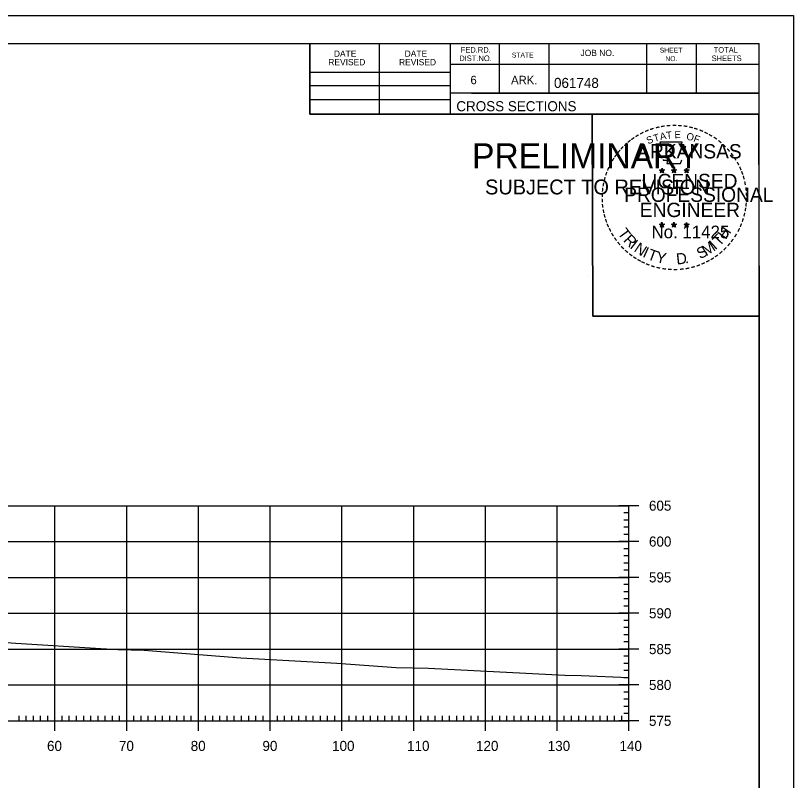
# Model space of a CAD drawing. Extents: x 961436 to 1372525, y 380079 to 2027791.
# Drawn here: x 1370245 to 1370353.4, y 380215.7 to 380322.4 of the extents above; entities that cross this region are included whole.
import ezdxf

# ---------------------------------------------------------------- set-up
doc = ezdxf.new("R2010")
doc.units = 0
for name, color, linetype in [('R_Axis', 7, 'Continuous'), ('R_Axis Annot', 7, 'Continuous'), ('R_Exist Surface', 7, 'Continuous'), ('R_Grid', 7, 'Continuous'), ('R_No Plot', 7, 'Continuous')]:
    doc.layers.add(name, color=color, linetype=linetype)

msp = doc.modelspace()

# ---------------------------------------------------------------- linework, layer by layer
at = {"layer": 'R_Axis'}
for p, q in [((1370331.9, 380254.06), (1370329.1, 380254.06)), ((1370330.5, 380224.06), (1370330.5, 380254.06)), ((1370330.5, 380253.06), (1370329.8, 380253.06)), ((1370330.5, 380252.06), (1370329.8, 380252.06)), ((1370330.5, 380251.06), (1370329.8, 380251.06)), ((1370330.5, 380250.06), (1370329.8, 380250.06)), ((1370331.9, 380249.06), (1370329.1, 380249.06)), ((1370330.5, 380248.06), (1370329.8, 380248.06)), ((1370330.5, 380247.06), (1370329.8, 380247.06)), ((1370330.5, 380246.06), (1370329.8, 380246.06)), ((1370330.5, 380245.06), (1370329.8, 380245.06)), ((1370331.9, 380244.06), (1370329.1, 380244.06)), ((1370330.5, 380243.06), (1370329.8, 380243.06)), ((1370330.5, 380242.06), (1370329.8, 380242.06)), ((1370330.5, 380241.06), (1370329.8, 380241.06)), ((1370330.5, 380240.06), (1370329.8, 380240.06)), ((1370331.9, 380239.06), (1370329.1, 380239.06)), ((1370330.5, 380238.06), (1370329.8, 380238.06)), ((1370330.5, 380237.06), (1370329.8, 380237.06)), ((1370330.5, 380236.06), (1370329.8, 380236.06)), ((1370330.5, 380235.06), (1370329.8, 380235.06)), ((1370331.9, 380234.06), (1370329.1, 380234.06)), ((1370330.5, 380233.06), (1370329.8, 380233.06)), ((1370330.5, 380232.06), (1370329.8, 380232.06)), ((1370330.5, 380231.06), (1370329.8, 380231.06)), ((1370330.5, 380230.06), (1370329.8, 380230.06)), ((1370331.9, 380229.06), (1370329.1, 380229.06)), ((1370330.5, 380228.06), (1370329.8, 380228.06)), ((1370330.5, 380227.06), (1370329.8, 380227.06)), ((1370250.5, 380222.66), (1370250.5, 380225.46)), ((1370260.5, 380222.66), (1370260.5, 380225.46)), ((1370270.5, 380222.66), (1370270.5, 380225.46)), ((1370280.5, 380222.66), (1370280.5, 380225.46)), ((1370290.5, 380222.66), (1370290.5, 380225.46)), ((1370300.5, 380222.66), (1370300.5, 380225.46)), ((1370310.5, 380222.66), (1370310.5, 380225.46)), ((1370320.5, 380222.66), (1370320.5, 380225.46)), ((1370330.5, 380226.06), (1370329.8, 380226.06)), ((1370330.5, 380222.66), (1370330.5, 380225.46)), ((1370050.5, 380224.06), (1370330.5, 380224.06)), ((1370245.5, 380224.06), (1370245.5, 380224.76)), ((1370246.5, 380224.06), (1370246.5, 380224.76)), ((1370247.5, 380224.06), (1370247.5, 380224.76)), ((1370248.5, 380224.06), (1370248.5, 380224.76)), ((1370249.5, 380224.06), (1370249.5, 380224.76)), ((1370251.5, 380224.06), (1370251.5, 380224.76)), ((1370252.5, 380224.06), (1370252.5, 380224.76)), ((1370253.5, 380224.06), (1370253.5, 380224.76)), ((1370254.5, 380224.06), (1370254.5, 380224.76)), ((1370255.5, 380224.06), (1370255.5, 380224.76)), ((1370256.5, 380224.06), (1370256.5, 380224.76)), ((1370257.5, 380224.06), (1370257.5, 380224.76)), ((1370258.5, 380224.06), (1370258.5, 380224.76)), ((1370259.5, 380224.06), (1370259.5, 380224.76)), ((1370261.5, 380224.06), (1370261.5, 380224.76)), ((1370262.5, 380224.06), (1370262.5, 380224.76)), ((1370263.5, 380224.06), (1370263.5, 380224.76)), ((1370264.5, 380224.06), (1370264.5, 380224.76)), ((1370265.5, 380224.06), (1370265.5, 380224.76)), ((1370266.5, 380224.06), (1370266.5, 380224.76)), ((1370267.5, 380224.06), (1370267.5, 380224.76)), ((1370268.5, 380224.06), (1370268.5, 380224.76)), ((1370269.5, 380224.06), (1370269.5, 380224.76)), ((1370271.5, 380224.06), (1370271.5, 380224.76)), ((1370272.5, 380224.06), (1370272.5, 380224.76)), ((1370273.5, 380224.06), (1370273.5, 380224.76)), ((1370274.5, 380224.06), (1370274.5, 380224.76)), ((1370275.5, 380224.06), (1370275.5, 380224.76)), ((1370276.5, 380224.06), (1370276.5, 380224.76)), ((1370277.5, 380224.06), (1370277.5, 380224.76)), ((1370278.5, 380224.06), (1370278.5, 380224.76)), ((1370279.5, 380224.06), (1370279.5, 380224.76)), ((1370281.5, 380224.06), (1370281.5, 380224.76)), ((1370282.5, 380224.06), (1370282.5, 380224.76)), ((1370283.5, 380224.06), (1370283.5, 380224.76)), ((1370284.5, 380224.06), (1370284.5, 380224.76)), ((1370285.5, 380224.06), (1370285.5, 380224.76)), ((1370286.5, 380224.06), (1370286.5, 380224.76)), ((1370287.5, 380224.06), (1370287.5, 380224.76)), ((1370288.5, 380224.06), (1370288.5, 380224.76)), ((1370289.5, 380224.06), (1370289.5, 380224.76)), ((1370291.5, 380224.06), (1370291.5, 380224.76)), ((1370292.5, 380224.06), (1370292.5, 380224.76)), ((1370293.5, 380224.06), (1370293.5, 380224.76)), ((1370294.5, 380224.06), (1370294.5, 380224.76)), ((1370295.5, 380224.06), (1370295.5, 380224.76)), ((1370296.5, 380224.06), (1370296.5, 380224.76)), ((1370297.5, 380224.06), (1370297.5, 380224.76)), ((1370298.5, 380224.06), (1370298.5, 380224.76)), ((1370299.5, 380224.06), (1370299.5, 380224.76)), ((1370301.5, 380224.06), (1370301.5, 380224.76)), ((1370302.5, 380224.06), (1370302.5, 380224.76)), ((1370303.5, 380224.06), (1370303.5, 380224.76)), ((1370304.5, 380224.06), (1370304.5, 380224.76)), ((1370305.5, 380224.06), (1370305.5, 380224.76)), ((1370306.5, 380224.06), (1370306.5, 380224.76)), ((1370307.5, 380224.06), (1370307.5, 380224.76)), ((1370308.5, 380224.06), (1370308.5, 380224.76)), ((1370309.5, 380224.06), (1370309.5, 380224.76)), ((1370311.5, 380224.06), (1370311.5, 380224.76)), ((1370312.5, 380224.06), (1370312.5, 380224.76)), ((1370313.5, 380224.06), (1370313.5, 380224.76)), ((1370314.5, 380224.06), (1370314.5, 380224.76)), ((1370315.5, 380224.06), (1370315.5, 380224.76)), ((1370316.5, 380224.06), (1370316.5, 380224.76)), ((1370317.5, 380224.06), (1370317.5, 380224.76)), ((1370318.5, 380224.06), (1370318.5, 380224.76)), ((1370319.5, 380224.06), (1370319.5, 380224.76)), ((1370321.5, 380224.06), (1370321.5, 380224.76)), ((1370322.5, 380224.06), (1370322.5, 380224.76)), ((1370323.5, 380224.06), (1370323.5, 380224.76)), ((1370324.5, 380224.06), (1370324.5, 380224.76)), ((1370325.5, 380224.06), (1370325.5, 380224.76)), ((1370326.5, 380224.06), (1370326.5, 380224.76)), ((1370327.5, 380224.06), (1370327.5, 380224.76)), ((1370328.5, 380224.06), (1370328.5, 380224.76)), ((1370331.9, 380224.06), (1370329.1, 380224.06)), ((1370329.5, 380224.06), (1370329.5, 380224.76)), ((1370330.5, 380225.06), (1370329.8, 380225.06))]:
    msp.add_line(p, q, dxfattribs=at)
at = {"layer": 'R_Exist Surface'}
msp.add_lwpolyline([(1370243.11, 380235.04), (1370245.03, 380234.91), (1370256.9, 380234.13), (1370259.27, 380234.01), (1370262.93, 380233.9), (1370276.43, 380232.83), (1370289.8, 380232.08), (1370298.07, 380231.5), (1370302.55, 380231.4), (1370321.57, 380230.45), (1370323.84, 380230.38), (1370330.5, 380230.11)], dxfattribs=at)
at = {"layer": 'R_Grid'}
for p, q in [((1370050.5, 380254.06), (1370330.5, 380254.06)), ((1370250.5, 380224.06), (1370250.5, 380254.06)), ((1370260.5, 380224.06), (1370260.5, 380254.06)), ((1370270.5, 380224.06), (1370270.5, 380254.06)), ((1370280.5, 380224.06), (1370280.5, 380254.06)), ((1370290.5, 380224.06), (1370290.5, 380254.06)), ((1370300.5, 380224.06), (1370300.5, 380254.06)), ((1370310.5, 380224.06), (1370310.5, 380254.06)), ((1370320.5, 380224.06), (1370320.5, 380254.06)), ((1370330.5, 380224.06), (1370330.5, 380254.06)), ((1370050.5, 380249.06), (1370330.5, 380249.06)), ((1370050.5, 380244.06), (1370330.5, 380244.06)), ((1370050.5, 380239.06), (1370330.5, 380239.06)), ((1370050.5, 380234.06), (1370330.5, 380234.06)), ((1370050.5, 380229.06), (1370330.5, 380229.06)), ((1370050.5, 380224.06), (1370330.5, 380224.06))]:
    msp.add_line(p, q, dxfattribs=at)
at = {"layer": 'R_No Plot'}
for p, q in [((1370020.1, 380322.41), (1370353.44, 380322.41)), ((1370032.5, 380318.52), (1370348.68, 380318.52)), ((1370286.04, 380308.64), (1370286.04, 380318.52)), ((1370295.72, 380308.64), (1370295.72, 380318.52)), ((1370305.58, 380318.52), (1370305.58, 380308.64)), ((1370312.42, 380318.52), (1370312.42, 380311.58)), ((1370319.36, 380318.52), (1370319.36, 380311.58)), ((1370332.94, 380318.52), (1370332.94, 380311.58)), ((1370339.88, 380318.52), (1370339.88, 380311.58)), ((1370348.68, 380113.06), (1370348.68, 380318.52)), ((1370348.68, 380315.58), (1370305.58, 380315.58)), ((1370348.68, 380315.6), (1370348.68, 380315.6)), ((1370286.04, 380314.5), (1370305.58, 380314.5)), ((1370286.04, 380312.64), (1370305.58, 380312.64)), ((1370348.68, 380311.58), (1370305.58, 380311.58)), ((1370308.54, 380311.58), (1370348.68, 380311.58)), ((1370286.04, 380310.7), (1370305.58, 380310.7)), ((1370348.68, 380308.64), (1370286.04, 380308.64)), ((1370335.12, 380301.15), (1370335.08, 380300.9)), ((1370335.12, 380300.78), (1370335.12, 380301.15)), ((1370335.12, 380301.15), (1370335.17, 380300.9)), ((1370336.79, 380301.15), (1370336.75, 380300.9)), ((1370336.79, 380300.78), (1370336.79, 380301.15)), ((1370336.79, 380301.15), (1370336.84, 380300.9)), ((1370338.55, 380301.14), (1370338.51, 380300.88)), ((1370338.55, 380300.77), (1370338.55, 380301.14)), ((1370338.55, 380301.14), (1370338.6, 380300.89)), ((1370334.77, 380300.89), (1370335.12, 380300.78)), ((1370334.77, 380300.89), (1370335.02, 380300.85)), ((1370334.77, 380300.89), (1370335.01, 380300.77)), ((1370334.9, 380300.49), (1370335.12, 380300.78)), ((1370334.9, 380300.49), (1370335.03, 380300.73)), ((1370334.9, 380300.49), (1370335.12, 380300.7)), ((1370335.47, 380300.89), (1370335.12, 380300.78)), ((1370335.33, 380300.49), (1370335.12, 380300.78)), ((1370335.33, 380300.49), (1370335.12, 380300.7)), ((1370335.47, 380300.89), (1370335.18, 380300.85)), ((1370335.33, 380300.49), (1370335.19, 380300.78)), ((1370335.47, 380300.89), (1370335.26, 380300.79)), ((1370336.44, 380300.89), (1370336.79, 380300.78)), ((1370336.44, 380300.89), (1370336.69, 380300.85)), ((1370336.44, 380300.89), (1370336.68, 380300.77)), ((1370336.57, 380300.49), (1370336.79, 380300.78)), ((1370336.57, 380300.49), (1370336.7, 380300.73)), ((1370336.57, 380300.49), (1370336.79, 380300.7)), ((1370337.14, 380300.89), (1370336.79, 380300.78)), ((1370337, 380300.49), (1370336.79, 380300.78)), ((1370337, 380300.49), (1370336.79, 380300.7)), ((1370337.14, 380300.89), (1370336.85, 380300.85)), ((1370337, 380300.49), (1370336.86, 380300.78)), ((1370337.14, 380300.89), (1370336.93, 380300.79)), ((1370338.2, 380300.88), (1370338.55, 380300.77)), ((1370338.2, 380300.88), (1370338.46, 380300.84)), ((1370338.2, 380300.88), (1370338.44, 380300.76)), ((1370338.34, 380300.47), (1370338.55, 380300.77)), ((1370338.34, 380300.47), (1370338.46, 380300.72)), ((1370338.34, 380300.47), (1370338.55, 380300.69)), ((1370338.9, 380300.88), (1370338.55, 380300.77)), ((1370338.77, 380300.47), (1370338.55, 380300.77)), ((1370338.77, 380300.47), (1370338.55, 380300.69)), ((1370338.9, 380300.88), (1370338.61, 380300.83)), ((1370338.77, 380300.47), (1370338.63, 380300.77)), ((1370338.9, 380300.88), (1370338.7, 380300.78)), ((1370335.11, 380293.58), (1370335.07, 380293.32)), ((1370335.11, 380293.21), (1370335.11, 380293.58)), ((1370335.11, 380293.58), (1370335.16, 380293.33)), ((1370336.78, 380293.58), (1370336.74, 380293.32)), ((1370336.78, 380293.21), (1370336.78, 380293.58)), ((1370336.78, 380293.58), (1370336.83, 380293.33)), ((1370338.55, 380293.57), (1370338.51, 380293.31)), ((1370338.55, 380293.2), (1370338.55, 380293.57)), ((1370338.55, 380293.57), (1370338.6, 380293.32)), ((1370334.77, 380293.32), (1370335.11, 380293.21)), ((1370334.77, 380293.32), (1370335.02, 380293.28)), ((1370334.77, 380293.32), (1370335, 380293.2)), ((1370334.9, 380292.91), (1370335.11, 380293.21)), ((1370334.9, 380292.91), (1370335.02, 380293.16)), ((1370334.9, 380292.91), (1370335.11, 380293.13)), ((1370335.46, 380293.32), (1370335.11, 380293.21)), ((1370335.33, 380292.91), (1370335.11, 380293.21)), ((1370335.33, 380292.91), (1370335.11, 380293.13)), ((1370335.46, 380293.32), (1370335.18, 380293.27)), ((1370335.33, 380292.91), (1370335.19, 380293.2)), ((1370335.46, 380293.32), (1370335.26, 380293.22)), ((1370336.43, 380293.32), (1370336.78, 380293.21)), ((1370336.43, 380293.32), (1370336.69, 380293.28)), ((1370336.43, 380293.32), (1370336.67, 380293.2)), ((1370336.57, 380292.91), (1370336.78, 380293.21)), ((1370336.57, 380292.91), (1370336.69, 380293.16)), ((1370336.57, 380292.91), (1370336.78, 380293.13)), ((1370337.13, 380293.32), (1370336.78, 380293.21)), ((1370337, 380292.91), (1370336.78, 380293.21)), ((1370337, 380292.91), (1370336.78, 380293.13)), ((1370337.13, 380293.32), (1370336.84, 380293.27)), ((1370337, 380292.91), (1370336.86, 380293.2)), ((1370337.13, 380293.32), (1370336.93, 380293.22)), ((1370338.2, 380293.31), (1370338.55, 380293.2)), ((1370338.2, 380293.31), (1370338.45, 380293.27)), ((1370338.2, 380293.31), (1370338.44, 380293.19)), ((1370338.33, 380292.9), (1370338.55, 380293.2)), ((1370338.33, 380292.9), (1370338.46, 380293.15)), ((1370338.33, 380292.9), (1370338.55, 380293.12)), ((1370338.9, 380293.31), (1370338.55, 380293.2)), ((1370338.76, 380292.9), (1370338.55, 380293.2)), ((1370338.76, 380292.9), (1370338.55, 380293.12)), ((1370338.9, 380293.31), (1370338.61, 380293.26)), ((1370338.76, 380292.9), (1370338.63, 380293.19)), ((1370338.9, 380293.31), (1370338.69, 380293.21)), ((1370324.72, 380286.18), (1370324.72, 380286.18))]:
    msp.add_line(p, q, dxfattribs=at)
for points in [[(1370020.1, 380322.41), (1370353.44, 380322.41), (1370353.44, 380109.08), (1370020.1, 380109.08)], [(1370266.42, 380318.52), (1370286.04, 380318.52), (1370286.04, 380308.64), (1370302.16, 380308.64), (1370325.36, 380308.64), (1370325.48, 380280.48), (1370348.68, 380280.48), (1370348.68, 380113.06), (1370032.5, 380113.06), (1370032.5, 380318.52)], [(1370325.36, 380308.64), (1370348.56, 380308.64), (1370348.68, 380280.48), (1370325.48, 380280.48)]]:
    msp.add_lwpolyline(points, close=True, dxfattribs=at)
for points in [[(1370334.81, 380304.77), (1370335.08, 380303.95)], [(1370338.32, 380303.85), (1370338.46, 380304.13), (1370337.78, 380304.11), (1370337.93, 380304.77), (1370334.81, 380304.77)], [(1370335.3, 380302.35), (1370335.3, 380302.26), (1370335.87, 380302.24), (1370335.81, 380301.77), (1370337.68, 380301.77), (1370337.88, 380302.31)], [(1370335.12, 380301.15), (1370335.33, 380300.49), (1370334.77, 380300.89), (1370335.47, 380300.89), (1370334.9, 380300.49), (1370335.12, 380301.15)], [(1370336.79, 380301.15), (1370337, 380300.49), (1370336.44, 380300.89), (1370337.14, 380300.89), (1370336.57, 380300.49), (1370336.79, 380301.15)], [(1370338.55, 380301.14), (1370338.77, 380300.47), (1370338.2, 380300.88), (1370338.9, 380300.88), (1370338.34, 380300.47), (1370338.55, 380301.14)], [(1370335.11, 380293.58), (1370335.33, 380292.91), (1370334.77, 380293.32), (1370335.46, 380293.32), (1370334.9, 380292.91), (1370335.11, 380293.58)], [(1370336.78, 380293.58), (1370337, 380292.91), (1370336.43, 380293.32), (1370337.13, 380293.32), (1370336.57, 380292.91), (1370336.78, 380293.58)], [(1370338.55, 380293.57), (1370338.76, 380292.9), (1370338.2, 380293.31), (1370338.9, 380293.31), (1370338.33, 380292.9), (1370338.55, 380293.57)]]:
    msp.add_lwpolyline(points, dxfattribs=at)
for centre, radius in [((1370335.12, 380300.78), 0.172), ((1370335.12, 380300.78), 0.145), ((1370335.12, 380300.78), 0.116), ((1370335.12, 380300.78), 0.0991), ((1370335.12, 380300.78), 0.0747), ((1370335.12, 380300.78), 0.0495), ((1370335.12, 380300.78), 0.0296), ((1370336.79, 380300.78), 0.172), ((1370336.79, 380300.78), 0.145), ((1370336.79, 380300.78), 0.116), ((1370336.79, 380300.78), 0.0991), ((1370336.79, 380300.78), 0.0747), ((1370336.79, 380300.78), 0.0495), ((1370336.79, 380300.78), 0.0296), ((1370338.55, 380300.77), 0.172), ((1370338.55, 380300.77), 0.145), ((1370338.55, 380300.77), 0.116), ((1370338.55, 380300.77), 0.0991), ((1370338.55, 380300.77), 0.0747), ((1370338.55, 380300.77), 0.0495), ((1370338.55, 380300.77), 0.0296), ((1370335.11, 380293.21), 0.172), ((1370335.11, 380293.21), 0.145), ((1370335.11, 380293.21), 0.116), ((1370335.11, 380293.21), 0.0991), ((1370335.11, 380293.21), 0.0747), ((1370335.11, 380293.21), 0.0495), ((1370335.11, 380293.21), 0.0296), ((1370336.78, 380293.21), 0.172), ((1370336.78, 380293.21), 0.145), ((1370336.78, 380293.21), 0.116), ((1370336.78, 380293.21), 0.0991), ((1370336.78, 380293.21), 0.0747), ((1370336.78, 380293.21), 0.0495), ((1370336.78, 380293.21), 0.0296), ((1370338.55, 380293.2), 0.172), ((1370338.55, 380293.2), 0.145), ((1370338.55, 380293.2), 0.116), ((1370338.55, 380293.2), 0.0991), ((1370338.55, 380293.2), 0.0747), ((1370338.55, 380293.2), 0.0495), ((1370338.55, 380293.2), 0.0296)]:
    msp.add_circle(centre, radius, dxfattribs=at)

# ---------------------------------------------------------------- texts
at = {"layer": 'R_Axis Annot'}
for s, p in [('605', (1370333.3, 380253.36)), ('600', (1370333.3, 380248.36)), ('595', (1370333.3, 380243.36)), ('590', (1370333.3, 380238.36)), ('585', (1370333.3, 380233.36)), ('580', (1370333.3, 380228.36)), ('575', (1370333.3, 380223.36)), ('60', (1370249.39, 380219.86)), ('70', (1370259.42, 380219.86)), ('80', (1370269.42, 380219.86)), ('90', (1370279.42, 380219.86)), ('100', (1370289.13, 380219.86)), ('110', (1370299.58, 380219.86)), ('120', (1370309.19, 380219.86)), ('130', (1370319.19, 380219.86)), ('140', (1370329.19, 380219.86))]:
    msp.add_text(s, height=1.4, dxfattribs=at).set_placement(p)
at = {"layer": 'R_No Plot'}
for s, height, rotation, p in [('DATE', 0.879, 360, (1370289.38, 380316.66)), ('DATE', 0.879, 360, (1370299.24, 380316.66)), ('FED.RD.', 0.782, 360, (1370307.06, 380317.24)), ('JOB NO.', 0.879, 360, (1370323.76, 380316.76)), ('SHEET', 0.684, 360, (1370334.8, 380317.24)), ('TOTAL', 0.782, 360, (1370342.32, 380317.24)), ('REVISED', 0.879, 360, (1370288.6, 380315.48)), ('REVISED', 0.879, 360, (1370298.46, 380315.48)), ('DIST.NO.', 0.782, 360, (1370306.86, 380316.06)), ('STATE', 0.684, 360, (1370314.18, 380316.56)), ('NO.', 0.684, 360, (1370335.58, 380316.06)), ('SHEETS', 0.782, 360, (1370342.04, 380316.06)), ('6', 1.17, 360, (1370308.42, 380312.84)), ('ARK.', 1.172, 360, (1370314.08, 380312.84)), ('061748', 1.4, 360, (1370320.06, 380312.32)), ('CROSS SECTIONS', 1.4, 360, (1370306.45, 380309.07)), ('-', 1.6, 24.3072, (1370332.92, 380305.63)), ('-', 1.6, 19.1761, (1370333.56, 380305.9)), ('-', 1.6, 13.6301, (1370334.31, 380306.14)), ('-', 1.6, 10.2193, (1370334.99, 380306.3)), ('-', 1.6, 5.8968, (1370335.72, 380306.41)), ('-', 1.6, 0.1862, (1370336.49, 380306.48)), ('-', 1.6, 357.743, (1370337.21, 380306.47)), ('-', 1.6, 352.1617, (1370337.95, 380306.42)), ('-', 1.6, 347.2049, (1370338.67, 380306.3)), ('-', 1.6, 342.3362, (1370339.31, 380306.15)), ('-', 1.6, 337.8551, (1370340.04, 380305.92)), ('-', 1.6, 36.2317, (1370331.12, 380304.55)), ('-', 1.6, 34.0636, (1370331.69, 380304.94)), ('-', 1.6, 28.7918, (1370332.29, 380305.31)), ('S', 1, 21.594, (1370333.17, 380304.45)), ('T', 1, 16.4036, (1370334.08, 380304.78)), ('A', 1, 11.2132, (1370334.91, 380305.03)), ('T', 1, 6.0228, (1370335.75, 380305.2)), ('E', 1, 0.8323, (1370336.86, 380305.31)), ('O', 1, 350.4515, (1370338.46, 380305.1)), ('F', 1, 340.0707, (1370339.42, 380304.87)), ('-', 1.6, 334.1211, (1370340.67, 380305.65)), ('-', 1.6, 329.6409, (1370341.25, 380305.37)), ('-', 1.6, 325.8627, (1370341.9, 380305.01)), ('PRELIMINARY', 3.5, 360, (1370308.64, 380301.1)), ('-', 1.6, 42.9622, (1370330.21, 380303.75)), ('-', 1.6, 38.9507, (1370330.64, 380304.17)), ('ARKANSAS', 2, 360, (1370331.66, 380302.48)), ('-', 1.6, 320.5297, (1370342.51, 380304.58)), ('-', 1.6, 315.5786, (1370343.11, 380304.09)), ('-', 1.6, 50.6142, (1370329.36, 380302.79)), ('-', 1.6, 48.423, (1370329.76, 380303.28)), ('-', 1.6, 309.8797, (1370343.67, 380303.54)), ('-', 1.6, 306.6522, (1370344.2, 380302.94)), ('DWB', 0.01, 360, (1370309.38, 380302.95)), ('-', 1.6, 58.0706, (1370328.62, 380301.7)), ('-', 1.6, 54.2325, (1370328.94, 380302.22)), ('-', 1.4, 303.6753, (1370344.69, 380302.37)), ('-', 1.6, 67.7743, (1370328.05, 380300.47)), ('-', 1.6, 62.8713, (1370328.31, 380301.08)), ('-', 1.6, 299.6684, (1370345, 380301.77)), ('-', 1.6, 294.6628, (1370345.33, 380301.16)), ('-', 1.6, 72.3945, (1370327.83, 380299.84)), ('LICENSED', 2, 360, (1370332.26, 380298.34)), ('DWB', 0.01, 360, (1370335.11, 380300.78)), ('DWB', 0.01, 360, (1370336.78, 380300.78)), ('DWB', 0.01, 360, (1370338.54, 380300.77)), ('-', 1.6, 290.5728, (1370345.59, 380300.58)), ('-', 1.6, 285.1233, (1370345.82, 380300)), ('SUBJECT TO REVISION', 2.0751, 360, (1370310.45, 380297.47)), ('-', 1.6, 81.2013, (1370327.5, 380298.41)), ('-', 1.6, 75.461, (1370327.63, 380299.13)), ('-', 1.6, 280.5493, (1370346.02, 380299.26)), ('-', 1.6, 85.1863, (1370327.42, 380297.72)), ('PROFESSIONAL', 2, 360, (1370329.84, 380296.43)), ('-', 1.6, 276.5962, (1370346.18, 380298.49)), ('-', 1.6, 94.1959, (1370327.43, 380296.3)), ('-', 1.6, 89.0622, (1370327.4, 380297.02)), ('-', 1.6, 274.3301, (1370346.24, 380297.77)), ('-', 1.6, 269.9407, (1370346.28, 380297.13)), ('-', 1.6, 98.9479, (1370327.5, 380295.63)), ('ENGINEER', 2, 360, (1370332.02, 380294.31)), ('-', 1.6, 260.9953, (1370346.19, 380295.81)), ('-', 1.6, 263.5172, (1370346.26, 380296.47)), ('-', 1.6, 101.7149, (1370327.64, 380294.9)), ('-', 1.6, 105.4578, (1370327.8, 380294.3)), ('-', 1.6, 255.7626, (1370346.08, 380295.14)), ('-', 1.6, 109.0874, (1370328.02, 380293.67)), ('-', 1.6, 247.8887, (1370345.67, 380293.74)), ('-', 1.6, 252.8681, (1370345.89, 380294.42)), ('-', 1.6, 114.0643, (1370328.27, 380293.07)), ('-', 1.6, 115.7289, (1370328.58, 380292.46)), ('T', 1.54, 306.0406, (1370328.87, 380292.05)), ('No. 11425', 1.757, 360, (1370333.65, 380291.36)), ('DWB', 0.01, 360, (1370335.1, 380293.21)), ('DWB', 0.01, 360, (1370336.77, 380293.21)), ('DWB', 0.01, 360, (1370338.54, 380293.2)), ('H', 1.54, 54.6088, (1370343.99, 380291.08)), ('-', 1.6, 244.6197, (1370345.41, 380293.11)), ('-', 1.6, 120.4471, (1370328.93, 380291.87)), ('-', 1.6, 125.8934, (1370329.34, 380291.31)), ('R', 1.54, 314.005, (1370329.64, 380291)), ('T', 1.54, 46.6444, (1370343.11, 380290.14)), ('-', 1.6, 233.8452, (1370344.61, 380291.71)), ('-', 1.6, 239.0712, (1370345.02, 380292.36)), ('-', 1.6, 130.7181, (1370329.8, 380290.76)), ('-', 1.6, 134.2238, (1370330.31, 380290.21)), ('I', 1.54, 321.9694, (1370330.54, 380290.07)), ('N', 1.54, 326.5002, (1370331.1, 380289.6)), ('S', 1.54, 26.9312, (1370340.42, 380288.41)), ('M', 1.54, 32.6563, (1370341.26, 380288.82)), ('I', 1.54, 42.1136, (1370342.54, 380289.66)), ('-', 1.6, 231.2538, (1370344.18, 380291.14)), ('-', 1.6, 138.9338, (1370330.84, 380289.75)), ('-', 1.6, 144.6463, (1370331.4, 380289.34)), ('I', 1.54, 335.3603, (1370332.31, 380288.81)), ('T', 1.54, 339.8912, (1370332.97, 380288.48)), ('Y', 1.54, 347.8556, (1370334.19, 380288.04)), ('D', 1.54, 6.3969, (1370337.18, 380287.68)), ('-', 1.6, 215.7363, (1370342.63, 380289.6)), ('-', 1.6, 221.0851, (1370343.18, 380290.07)), ('-', 1.6, 225.7653, (1370343.7, 380290.58)), ('-', 1.6, 148.0898, (1370331.96, 380288.97)), ('-', 1.6, 151.5704, (1370332.54, 380288.65)), ('-', 1.6, 154.6002, (1370333.06, 380288.4)), ('.', 1.54, 13.7642, (1370338.37, 380287.81)), ('-', 1.6, 204.2516, (1370340.92, 380288.55)), ('-', 1.6, 207.3568, (1370341.54, 380288.87)), ('-', 1.6, 212.2491, (1370342.1, 380289.21)), ('-', 1.6, 158.5612, (1370333.68, 380288.15)), ('-', 1.6, 162.7983, (1370334.37, 380287.93)), ('-', 1.6, 167.5555, (1370335.08, 380287.77)), ('-', 1.6, 173.1155, (1370335.86, 380287.66)), ('-', 1.6, 176.5183, (1370336.6, 380287.61)), ('-', 1.6, 181.5918, (1370337.35, 380287.62)), ('-', 1.6, 185.8167, (1370338.16, 380287.7)), ('-', 1.6, 191.2858, (1370338.89, 380287.83)), ('-', 1.6, 195.4743, (1370339.62, 380288.03)), ('-', 1.6, 200.7184, (1370340.3, 380288.27))]:
    msp.add_text(s, height=height, rotation=rotation, dxfattribs=at).set_placement(p)

doc.saveas('drawing.dxf')
